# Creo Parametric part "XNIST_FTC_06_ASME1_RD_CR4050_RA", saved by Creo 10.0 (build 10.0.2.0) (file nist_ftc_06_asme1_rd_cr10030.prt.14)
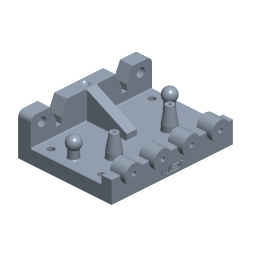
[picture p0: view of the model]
Units: Inch lbm Second (Pro/E Default); INCH, POUND, SECS

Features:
  1. datum plane "RIGHT"
  2. datum plane "TOP"
  3. datum plane "FRONT"
  4. coordinate system
  5. protrusion
  6. datum plane "MIDPLANE"
  7. pattern
  8. protrusion
  9. protrusion
  10. protrusion
  11. protrusion
  12. cut
  13. curve
  14. curve
  15. datum plane "MIDPLANE_DTM_J"
  16. cut
  17. curve
  18. curve
  19. datum plane "MIDPLANE_DTM_K"
  20. datum plane "CONE_CENTERS"
  21. protrusion
  22. hole
  23. protrusion
  24. hole
  25. datum plane "SPHERE_CENTERS"
  26. protrusion
  27. protrusion
  28. pattern
  29. hole
  30. hole
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
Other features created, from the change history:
  datum plane "DTM1"

Other named items: LOCAL_GROUP, LOCAL_GROUP_1, COPIED_GROUP_1, CONE_GAGE_CIRCLES, COPIED_GROUP, CONE_GAGE_HEIGHT, DRF_A, DRF_AB, CS2, DRF_DBC, CS4, DRF_D, CS6, CS7, CS8, DRF_F, DRF_DG, DRF_DH, DRF_DCJ, DRF_DCK, CS14, DRF_ABC, AD138, AD140, AD144, AD148, AD153, AD156, GP23, , AD212, GP26, AD213, GP27, AD214, GP28, AD215, GP29, AD216, GP30, AD217, GP31, AD218, AD219, RD8, GP32, DATUM_TAG_A, GP33, GP34, DATUM_TAG_D, NOTE_38, DATUM_TAG_F, DRF16, DRF17, AD222, GP35, DATUM_TAG_B, GP36, DATUM_TAG_C, GP37, GP38, GP39, DATUM_TAG_E, GP40, GP41, NOTE_46, NOTE_47, AD223, GP42, AD224, GP43, AD226, GP44, AD228, GP45, RD21, RD25, RD31, RD34, GP46, GP47, DT7, DATUM_TAG_G, DT8, DATUM_TAG_H, DATUM_TAG_J, DATUM_TAG_K, DT9, DT10, DT11, DT12, MBD_A, MBD_B, MBD_C, ANNOT_LAYER_STATE0001, ANNOT_LAYER_STATE0002, ANNOT_LAYER_STATE0003

Layers: ALL_ANNOTATIONS, ALL_AXES, ALL_CSYS, ALL_CURVES, ALL_PLANES, ALL_POINTS, ALL_QUILTS, DEF_CSYS, DEF_PLANES

Notes: 2X 1.00 : 3.00 | 1.00 : 2.00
